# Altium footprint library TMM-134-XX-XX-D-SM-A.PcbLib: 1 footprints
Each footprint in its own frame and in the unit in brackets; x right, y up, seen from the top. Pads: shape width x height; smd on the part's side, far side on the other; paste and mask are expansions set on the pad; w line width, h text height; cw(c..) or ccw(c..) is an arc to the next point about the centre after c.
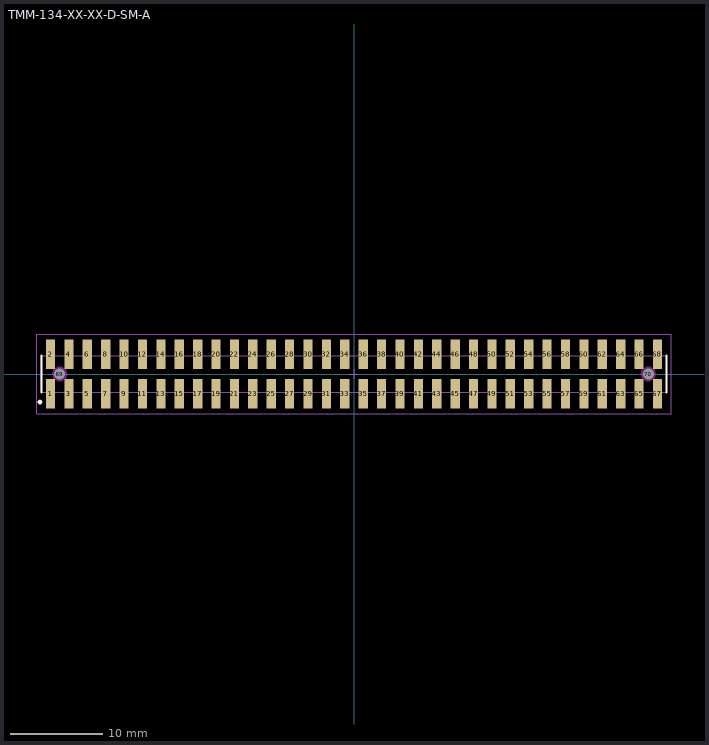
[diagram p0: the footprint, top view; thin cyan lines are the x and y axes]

## TMM-134-XX-XX-D-SM-A [mm] "2.00mm pitch, 68 pin, terminal strip; double row, w/alignment pins, SMT"
height 2.77
pads (70):
  rect 1x3.2 smd mask+0: 1(-33,-2.15) 2(-33,2.15) 3(-31,-2.15) 4(-31,2.15) 5(-29,-2.15) 6(-29,2.15) 7(-27,-2.15) 8(-27,2.15) 9(-25,-2.15) 10(-25,2.15) 11(-23,-2.15) 12(-23,2.15) 13(-21,-2.15) 14(-21,2.15) 15(-19,-2.15) 16(-19,2.15) 17(-17,-2.15) 18(-17,2.15) 19(-15,-2.15) 20(-15,2.15) 21(-13,-2.15) 22(-13,2.15) 23(-11,-2.15) 24(-11,2.15) 25(-9,-2.15) 26(-9,2.15) 27(-7,-2.15) 28(-7,2.15) 29(-5,-2.15) 30(-5,2.15) 31(-3,-2.15) 32(-3,2.15) 33(-1,-2.15) 34(-1,2.15) 35(1,-2.15) 36(1,2.15) 37(3,-2.15) 38(3,2.15) 39(5,-2.15) 40(5,2.15) 41(7,-2.15) 42(7,2.15) 43(9,-2.15) 44(9,2.15) 45(11,-2.15) 46(11,2.15) 47(13,-2.15) 48(13,2.15) 49(15,-2.15) 50(15,2.15) 51(17,-2.15) 52(17,2.15) 53(19,-2.15) 54(19,2.15) 55(21,-2.15) 56(21,2.15) 57(23,-2.15) 58(23,2.15) 59(25,-2.15) 60(25,2.15) 61(27,-2.15) 62(27,2.15) 63(29,-2.15) 64(29,2.15) 65(31,-2.15) 66(31,2.15) 67(33,-2.15) 68(33,2.15)
  round 1 hole 1.2 unplated mask+0: 69(-32,0) 70(32,0)
Top Overlay:
  circle w0.25: c-34.15,-3.05 r0.125
  lines w0.2: -34,-2 -34,2 ; 34,-2 34,2
Keep-Out Layer:
  pour cut-out: -31.193,0 -31.22,0.209 -31.301,0.403 -31.429,0.571 -31.596,0.699 -31.791,0.779 -32,0.807 -32.209,0.779 -32.403,0.699 -32.57,0.571 -32.699,0.403 -32.779,0.209 -32.807,0 -32.779,-0.209 -32.699,-0.403 -32.57,-0.571 -32.403,-0.699 -32.209,-0.779 -32,-0.807 -31.791,-0.779 -31.596,-0.699 -31.429,-0.571 -31.301,-0.403 -31.22,-0.209
  pour cut-out: 32.807,0 32.779,0.209 32.699,0.403 32.57,0.571 32.403,0.699 32.209,0.779 32,0.807 31.791,0.779 31.596,0.699 31.429,0.571 31.301,0.403 31.22,0.209 31.193,0 31.22,-0.209 31.301,-0.403 31.429,-0.571 31.596,-0.699 31.791,-0.779 32,-0.807 32.209,-0.779 32.403,-0.699 32.57,-0.571 32.699,-0.403 32.779,-0.209
Mechanical 12:
  lines w0.001: -34,-2 34,-2 34,2 -34,2 -34,-2
Mechanical 13:
  lines w0.1: -34,-2 34,-2 34,2 -34,2 -34,-2
  text ".Designator" at 0,-0.127 h1.52
Mechanical 15:
  lines w0.05: -0.5,0 0.5,0 ; 0,-0.5 0,0.5 ; -34.5,-4.3 34.5,-4.3 34.5,4.3 -34.5,4.3 -34.5,-4.3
